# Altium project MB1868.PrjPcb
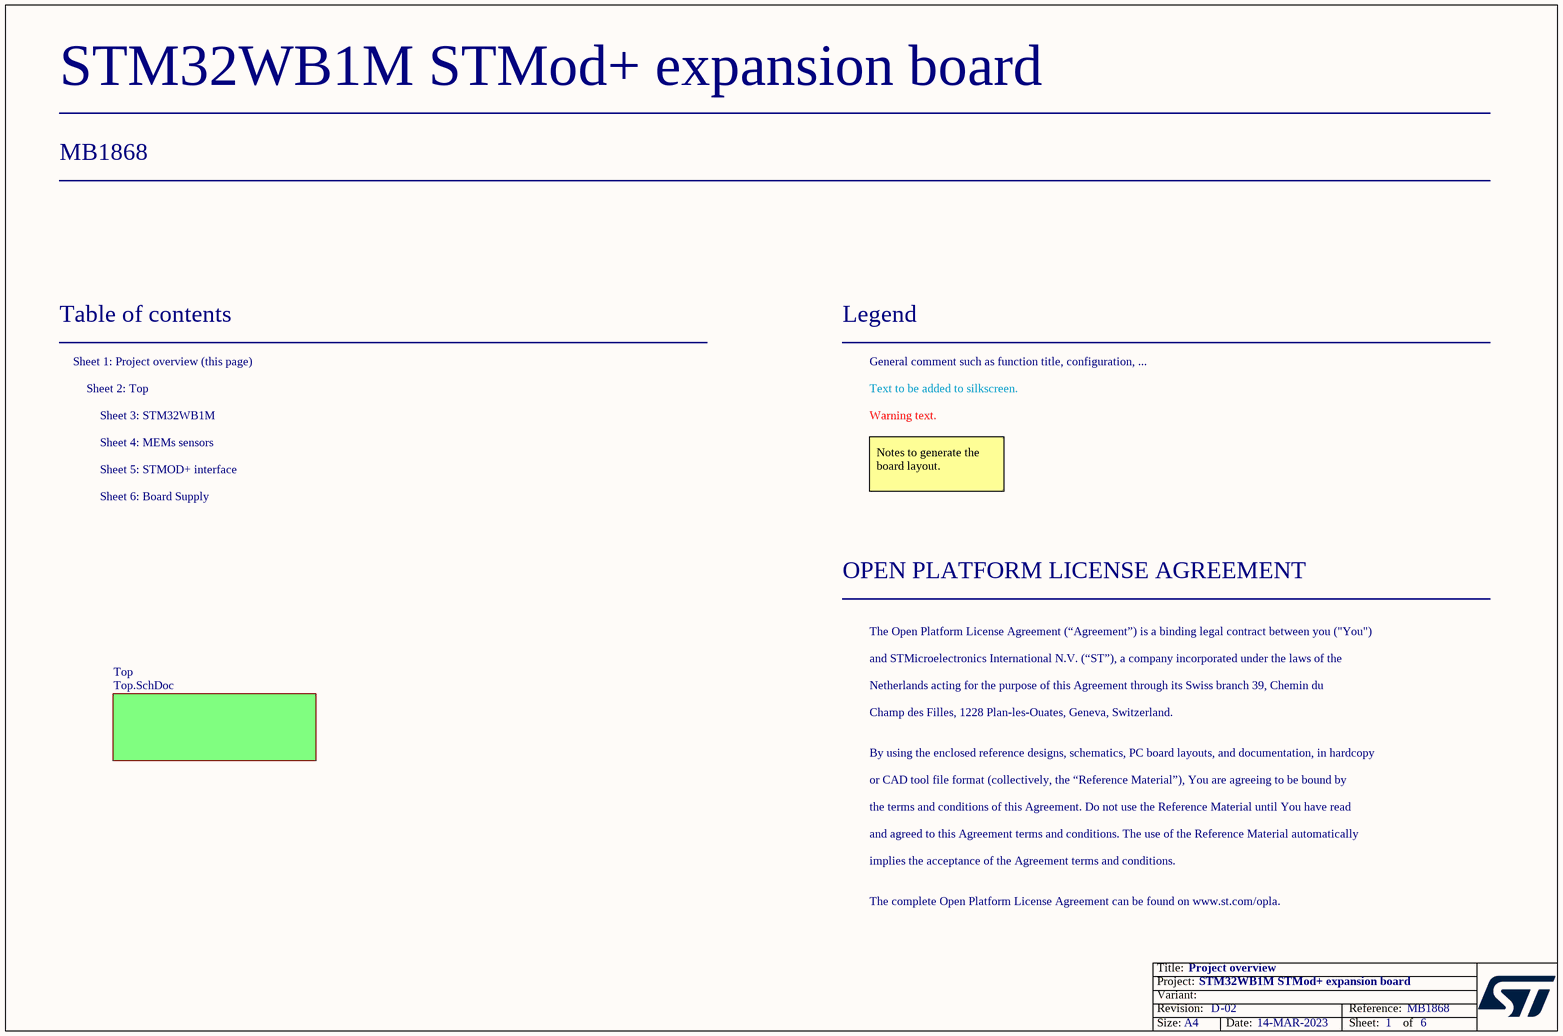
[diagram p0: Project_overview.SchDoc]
Board_Reference: MB1868; Board_PCB_Revision: D; Board_Name: STM32WB1M STMod+ expansion board; Board_Document_Date: 14-MAR-2023; Board_Assembly_Revision: 02
6 sheets, 72 parts. Net scope: flat (ports and power ports of the same name join across sheets).
Board file: MB1868.PcbDoc
Sheets:
  Project_overview.SchDoc
    Top = Top.SchDoc
      U_Mems = Mems.SchDoc
      U_STM32WB1M = STM32WB1M.SchDoc
      U_Board_supply = Board_supply.SchDoc
      U_STMOD+_interface = STMOD+_interface.SchDoc

## Sheet Project_overview.SchDoc: Project overview
size A4; Date: Not used; ApprovedBy: Not used; CheckedBy: Not used; Author: Not used; CompanyName: STMicroelectronics; DrawnBy: Not used; Engineer: Not used; Organization: Not used; Address1: Not used; Address2: Not used; Address3: Not used; Address4: Not used; DocumentNumber: Not used; Revision: Not used; SheetNumber: 1; SheetTotal: 6

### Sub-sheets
Top = Top.SchDoc: no entries

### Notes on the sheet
- Table of contents
- Sheet 1: Project overview (this page)
- Legend
- General comment such as function title, configuration, ...
- Sheet 2: Top
- Sheet 3: STM32WB1M
- Sheet 4: MEMs sensors
- Text to be added to silkscreen.
- Warning text.
- Sheet 6: Board Supply
- Sheet 5: STMOD+ interface
- Notes to generate the board layout.
- OPEN PLATFORM LICENSE AGREEMENT
- The Open Platform License Agreement (“Agreement”) is a binding legal contract between you ("You")
- and STMicroelectronics International N.V. (“ST”), a company incorporated under the laws of the
- Netherlands acting for the purpose of this Agreement through its Swiss branch 39, Chemin du
- Champ des Filles, 1228 Plan-les-Ouates, Geneva, Switzerland.
- By using the enclosed reference designs, schematics, PC board layouts, and documentation, in hardcopy
- or CAD tool file format (collectively, the “Reference Material”), You are agreeing to be bound by
- the terms and conditions of this Agreement. Do not use the Reference Material until You have read
- and agreed to this Agreement terms and conditions. The use of the Reference Material automatically
- implies the acceptance of the Agreement terms and conditions.
- The complete Open Platform License Agreement can be found on www.st.com/opla.

## Sheet Top.SchDoc: Top hierarchical view
size A4; Date: Not used; ApprovedBy: Not used; CheckedBy: Not used; Author: Not used; CompanyName: STMicroelectronics; DrawnBy: Not used; Engineer: Not used; Organization: Not used; Address1: Not used; Address2: Not used; Address3: Not used; Address4: Not used; DocumentNumber: Not used; Revision: Not used; SheetNumber: 2; SheetTotal: 6
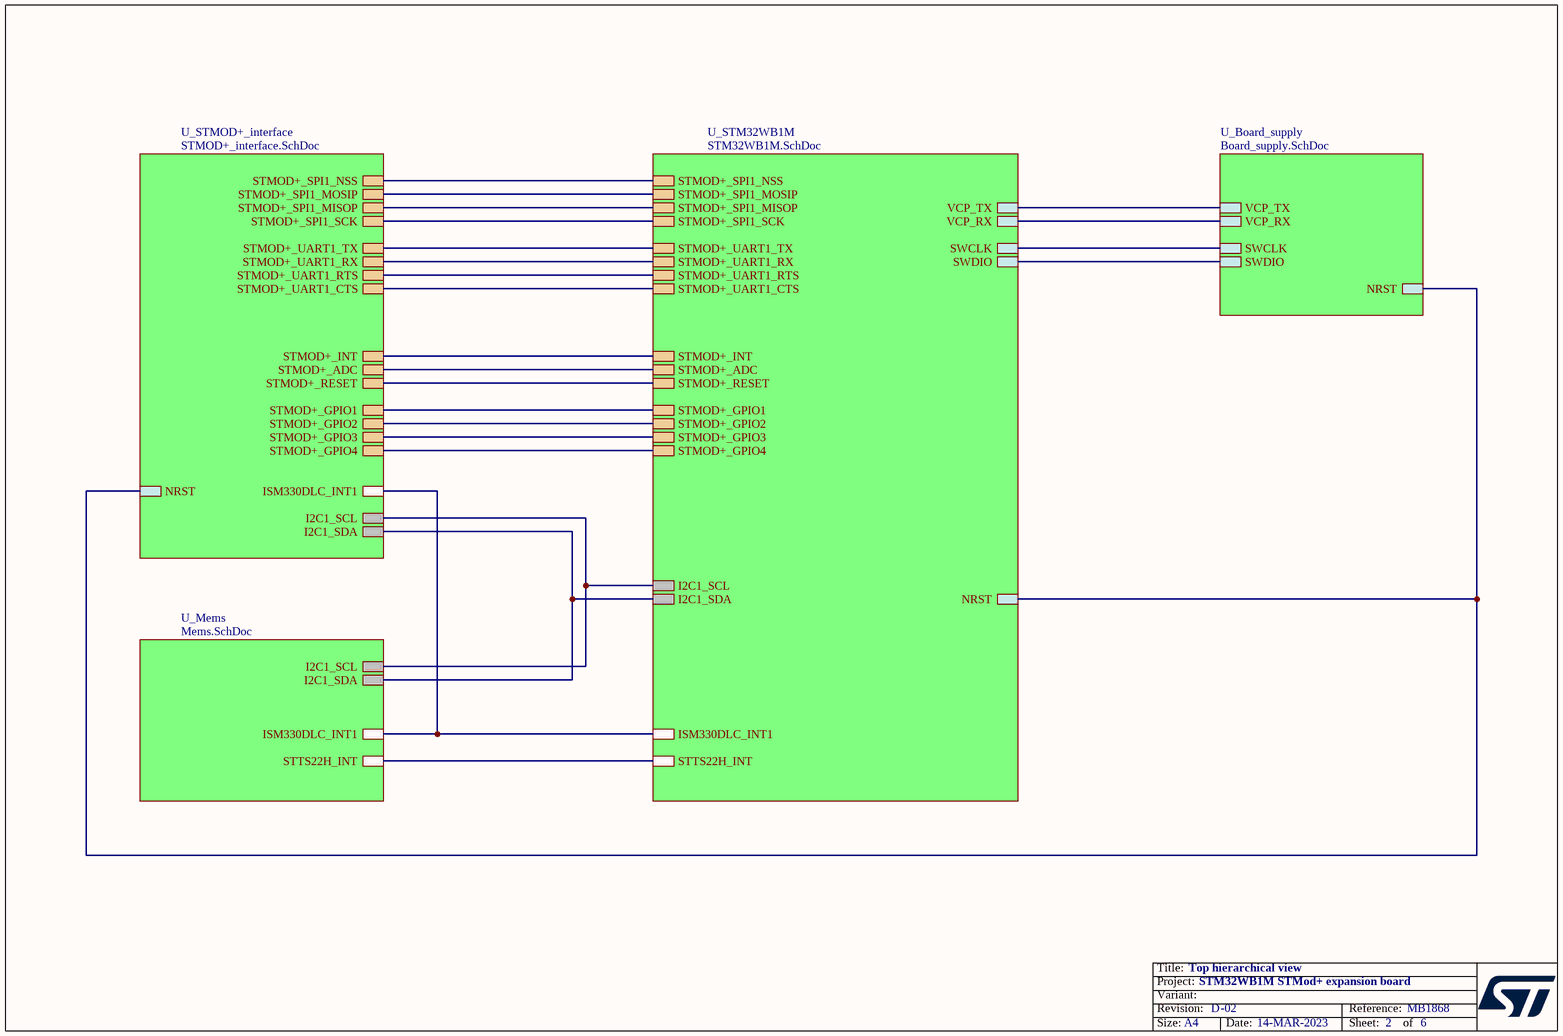
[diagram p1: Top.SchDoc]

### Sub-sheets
U_Board_supply = Board_supply.SchDoc: SWCLK, NRST, SWDIO, VCP_TX, VCP_RX
U_Mems = Mems.SchDoc: STTS22H_INT, ISM330DLC_INT1, I2C1_SCL, I2C1_SDA
U_STM32WB1M = STM32WB1M.SchDoc: VCP_TX, VCP_RX, SWCLK, SWDIO, ISM330DLC_INT1, STTS22H_INT, STMOD+_UART1_RX, STMOD+_UART1_TX, STMOD+_GPIO2, STMOD+_GPIO1, STMOD+_SPI1_SCK, STMOD+_SPI1_MOSIP, STMOD+_RESET, STMOD+_GPIO3, STMOD+_SPI1_NSS, STMOD+_UART1_RTS, STMOD+_INT, STMOD+_ADC, STMOD+_UART1_CTS, STMOD+_SPI1_MISOP, NRST, I2C1_SCL, I2C1_SDA, STMOD+_GPIO4
U_STMOD+_interface = STMOD+_interface.SchDoc: I2C1_SCL, I2C1_SDA, STMOD+_SPI1_MOSIP, STMOD+_UART1_TX, STMOD+_UART1_RX, STMOD+_SPI1_SCK, STMOD+_UART1_RTS, STMOD+_GPIO1, STMOD+_SPI1_NSS, STMOD+_INT, STMOD+_GPIO3, STMOD+_RESET, STMOD+_GPIO2, NRST, ISM330DLC_INT1, STMOD+_ADC, STMOD+_UART1_CTS, STMOD+_SPI1_MISOP, STMOD+_GPIO4

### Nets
(unnamed): sheet U_Mems/STTS22H_INT, sheet U_STM32WB1M/STTS22H_INT
(unnamed): sheet U_Mems/ISM330DLC_INT1, sheet U_STM32WB1M/ISM330DLC_INT1, sheet U_STMOD+_interface/ISM330DLC_INT1  [a separate net that carries the same name]
(unnamed): sheet U_Mems/I2C1_SCL, sheet U_STM32WB1M/I2C1_SCL, sheet U_STMOD+_interface/I2C1_SCL  [a separate net that carries the same name]
(unnamed): sheet U_Mems/I2C1_SDA, sheet U_STM32WB1M/I2C1_SDA, sheet U_STMOD+_interface/I2C1_SDA  [a separate net that carries the same name]
(unnamed): sheet U_STM32WB1M/VCP_TX, sheet U_Board_supply/VCP_TX  [a separate net that carries the same name]
(unnamed): sheet U_STM32WB1M/VCP_RX, sheet U_Board_supply/VCP_RX  [a separate net that carries the same name]
(unnamed): sheet U_STM32WB1M/SWCLK, sheet U_Board_supply/SWCLK  [a separate net that carries the same name]
(unnamed): sheet U_STM32WB1M/SWDIO, sheet U_Board_supply/SWDIO  [a separate net that carries the same name]
(unnamed): sheet U_STM32WB1M/STMOD+_UART1_RX, sheet U_STMOD+_interface/STMOD+_UART1_RX  [a separate net that carries the same name]
(unnamed): sheet U_STM32WB1M/STMOD+_UART1_TX, sheet U_STMOD+_interface/STMOD+_UART1_TX  [a separate net that carries the same name]
(unnamed): sheet U_STM32WB1M/STMOD+_GPIO2, sheet U_STMOD+_interface/STMOD+_GPIO2  [a separate net that carries the same name]
(unnamed): sheet U_STM32WB1M/STMOD+_GPIO1, sheet U_STMOD+_interface/STMOD+_GPIO1  [a separate net that carries the same name]
(unnamed): sheet U_STM32WB1M/STMOD+_SPI1_SCK, sheet U_STMOD+_interface/STMOD+_SPI1_SCK  [a separate net that carries the same name]
(unnamed): sheet U_STM32WB1M/STMOD+_SPI1_MOSIP, sheet U_STMOD+_interface/STMOD+_SPI1_MOSIP  [a separate net that carries the same name]
(unnamed): sheet U_STM32WB1M/STMOD+_RESET, sheet U_STMOD+_interface/STMOD+_RESET  [a separate net that carries the same name]
(unnamed): sheet U_STM32WB1M/STMOD+_GPIO3, sheet U_STMOD+_interface/STMOD+_GPIO3  [a separate net that carries the same name]
(unnamed): sheet U_STM32WB1M/STMOD+_SPI1_NSS, sheet U_STMOD+_interface/STMOD+_SPI1_NSS  [a separate net that carries the same name]
(unnamed): sheet U_STM32WB1M/STMOD+_UART1_RTS, sheet U_STMOD+_interface/STMOD+_UART1_RTS  [a separate net that carries the same name]
(unnamed): sheet U_STM32WB1M/STMOD+_INT, sheet U_STMOD+_interface/STMOD+_INT  [a separate net that carries the same name]
(unnamed): sheet U_STM32WB1M/STMOD+_ADC, sheet U_STMOD+_interface/STMOD+_ADC  [a separate net that carries the same name]
(unnamed): sheet U_STM32WB1M/STMOD+_UART1_CTS, sheet U_STMOD+_interface/STMOD+_UART1_CTS  [a separate net that carries the same name]
(unnamed): sheet U_STM32WB1M/STMOD+_SPI1_MISOP, sheet U_STMOD+_interface/STMOD+_SPI1_MISOP  [a separate net that carries the same name]
(unnamed): sheet U_STM32WB1M/NRST, sheet U_Board_supply/NRST, sheet U_STMOD+_interface/NRST  [a separate net that carries the same name]
(unnamed): sheet U_STM32WB1M/STMOD+_GPIO4, sheet U_STMOD+_interface/STMOD+_GPIO4  [a separate net that carries the same name]

## Sheet Mems.SchDoc: Mems Sensors
size A4; Date: Not used; ApprovedBy: Not used; CheckedBy: Not used; Author: Not used; CompanyName: STMicroelectronics; DrawnBy: Not used; Engineer: Not used; Organization: Not used; Address1: Not used; Address2: Not used; Address3: Not used; Address4: Not used; DocumentNumber: Not used; Revision: Not used; SheetNumber: 5; SheetTotal: 6
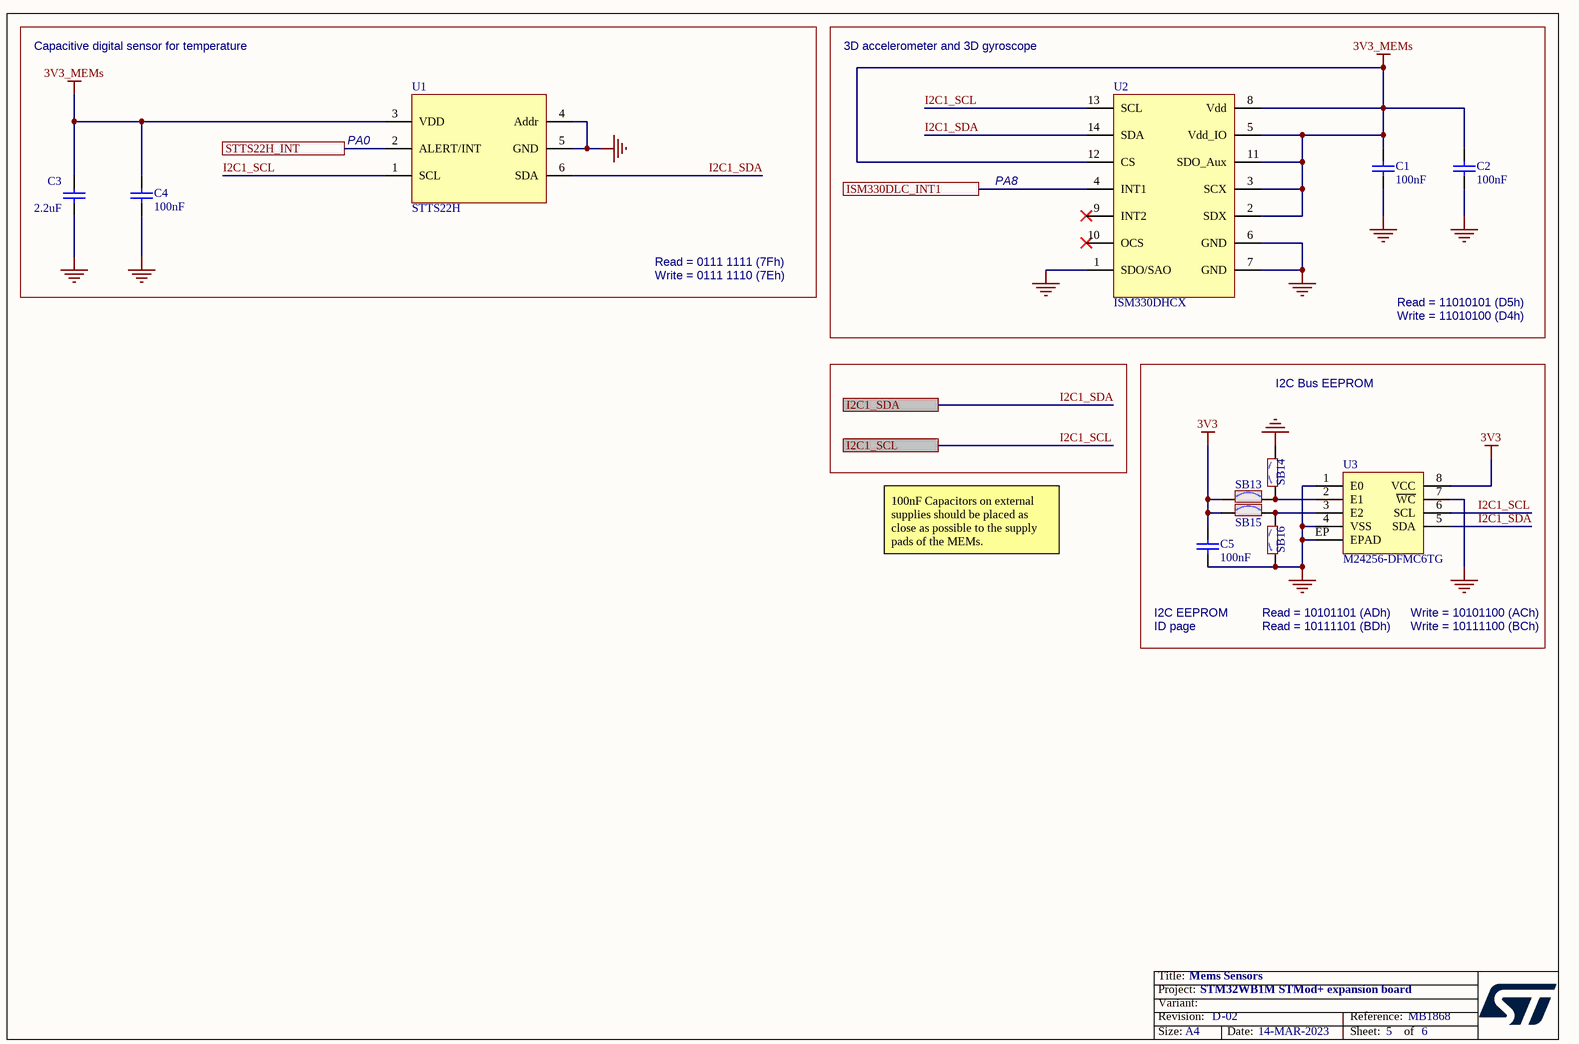
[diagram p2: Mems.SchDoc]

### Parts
C1  value 100nF  [C0402]  (hidden comment: Capacitor)
C2  value 100nF  [C0402]  (hidden comment: Capacitor)
C3  value 2.2uF  [C0402]  (hidden comment: Capacitor)
C4  value 100nF  [C0402]  (hidden comment: Capacitor)
C5  value 100nF  [C0402]  (hidden comment: Capacitor)
SB13  SB_ON  [SOLDER-BRIDGE_R0402-0R]  (value not drawn)
SB14  SB_OFF  [SOLDER-BRIDGE_R0402-0R]  (value not drawn)
SB15  SB_ON  [SOLDER-BRIDGE_R0402-0R]  (value not drawn)
SB16  SB_OFF  [SOLDER-BRIDGE_R0402-0R]  (value not drawn)
U1  STTS22H  [ICC_UDFN6-EPAD_2X2_P065]
U2  ISM330DHCX  [ICC_LGA14_3X2P5_P050]
U3  value M24256-DFMC6TG  [ICC_DFN8-EPAD_2X3_P050]  (hidden comment: M24128-DFMC6TP)

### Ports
I2C1_SCL, I2C1_SDA, ISM330DLC_INT1, STTS22H_INT

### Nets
3V3: C5.2 SB13.1 SB15.1 U3.8(VCC)
3V3_MEMs: C1.2 C2.2 C3.2 C4.2 U1.3(VDD) U2.2(SDX) U2.3(SCX) U2.5(Vdd_IO) U2.8(Vdd) U2.11(SDO_Aux) U2.12(CS)
GND: C1.1 C2.1 C3.1 C4.1 C5.1 SB14.1 SB16.2 U1.4(Addr) U1.5(GND) U2.1(SDO/SAO) U2.6(GND) U2.7(GND) U3.1(E0) U3.4(VSS) U3.7(~{WC}) U3.EP(EPAD)
I2C1_SCL: U1.1(SCL) U2.13(SCL) U3.6(SCL) ; port I2C1_SCL
I2C1_SDA: U1.6(SDA) U2.14(SDA) U3.5(SDA) ; port I2C1_SDA
PA0: U1.2(ALERT/INT) ; port STTS22H_INT
PA8: U2.4(INT1) ; port ISM330DLC_INT1
NetSB13_2: SB13.2 SB14.2 U3.2(E1)
NetSB15_2: SB15.2 SB16.1 U3.3(E2)

Not connected (* = marked no-connect by the designer): U2 9(INT2)* 10(OCS)*

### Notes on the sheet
- Capacitive digital sensor for temperature
- 3D accelerometer and 3D gyroscope
- (near U1) PA0
- PA8
- Read = 0111 1111 (7Fh)
- Write = 0111 1110 (7Eh)
- Read = 11010101 (D5h)
- Write = 11010100 (D4h)
- I2C Bus EEPROM
- 100nF Capacitors on external supplies should be placed as close as possible to the supply pads of the MEMs.
- I2C EEPROM
- ID page
- Read = 10101101 (ADh)
- Read = 10111101 (BDh)
- Write = 10101100 (ACh)
- Write = 10111100 (BCh)

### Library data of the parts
C1 C2 C4 C5 = MCD-00006: Capacitor, MLCC, 100nF, 16V, X7R, +/-10%, 0402, T=0.5mm; Part_Preference: Recommended; Manufacturer: YAGEO; Manufacturer_Part_Number: CC0402KRX7R7BB104; Partial_Alternate_Internal_Part_Number: MCD-03299; Order_Code_RS: 616-9701; Component_Country_Of_Origin: China; ShowFields: YES; ID: 2474
C3 = MCD-01823: Capacitor, MLCC, 2.2uF, 6V3, X5R,+/-10%, 0402, T=0.5mm; Manufacturer_Part_Number: GRM155R60J225KE95D; Manufacturer: MURATA; Part_Preference: Recommended; Order_Code_RS: 172-6478
SB13 SB15 = MCD-01618: Solder Bridge 0402 ON; Part_Type: Misc; Manufacturer_Part_Number: RC0402JR-070RL; Manufacturer: YAGEO; Part_Preference: Recommended; Order_Code_RS: 618-5804
SB14 SB16 = MCD-02162: Solder Bridge 0402 OFF; Part_Type: Misc; Part_Preference: Recommended; Manufacturer: YAGEO; Manufacturer_Part_Number: RC0402JR-070RL; Order_Code_RS: 618-5804
U1 = MCD-02159: temperature sensor; Part_Type: IC; Part_Preference: Recommended; Manufacturer: STMICROELECTRONICS; Manufacturer_HQ_COO: EU; Order_code_RS: 194-7646; Component_Country_Of_Origin: Thailand
U2 = MCD-02160: iNEMO inertial module: 3D accelerometer and 3D gyroscope, with digital output for industrial applications; Part_Type: IC; Part_Preference: Recommended; Manufacturer: STMICROELECTRONICS; Manufacturer_HQ_COO: EU; Order_code_RS: ISM330DHCXTR; Component_Country_Of_Origin: Malta, Philippines
U3 = MCD-01871: I2C Memory 3V3, 256Kbits, 2x3,0.55mm, UFDFPN8; Part_Type: IC; Manufacturer: STMICROELECTRONICS; BMS_Part_Number: 9175665; Part_Preference: Recommended; Manufacturer_HQ_COO: EU

## Sheet STM32WB1M.SchDoc: STM32WB1M
size A4; Date: Not used; ApprovedBy: Not used; CheckedBy: Not used; Author: Not used; CompanyName: STMicroelectronics; DrawnBy: Not used; Engineer: Not used; Organization: Not used; Address1: Not used; Address2: Not used; Address3: Not used; Address4: Not used; DocumentNumber: Not used; Revision: Not used; SheetNumber: 3; SheetTotal: 6
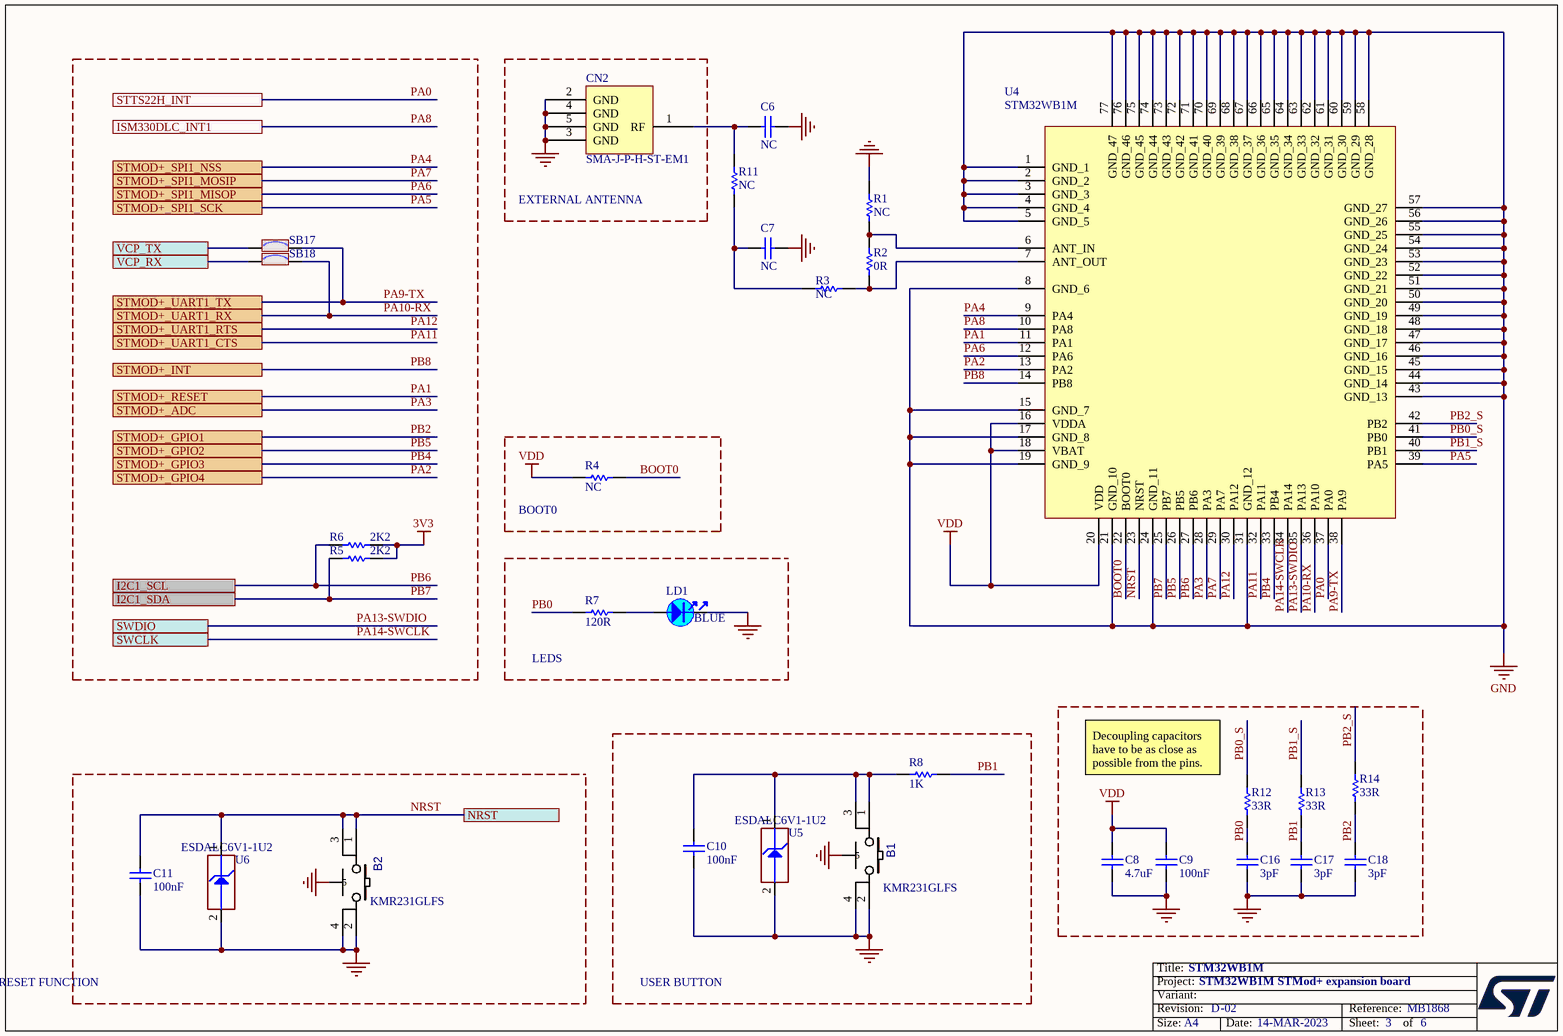
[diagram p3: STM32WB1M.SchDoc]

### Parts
B1  value KMR231GLFS  [SWI_C&K_Y78B23110FP__ITT_KMR231GLFS]
B2  value KMR231GLFS  [SWI_C&K_Y78B23110FP__ITT_KMR231GLFS]
C6  value NC  [C0402]  (hidden comment: Capacitor)
C7  value NC  [C0402]  (hidden comment: Capacitor)
C8  value 4.7uF  [C0603]
C9  value 100nF  [C0402]  (hidden comment: Capacitor)
C10  value 100nF  [C0402]  (hidden comment: Capacitor)
C11  value 100nF  [C0402]  (hidden comment: Capacitor)
C16  value 3pF  [CC0201CRNPO8BN3R0]  (hidden comment: Capacitor)
C17  value 3pF  [CC0201CRNPO8BN3R0]  (hidden comment: Capacitor)
C18  value 3pF  [CC0201CRNPO8BN3R0]  (hidden comment: Capacitor)
CN2  value SMA-J-P-H-ST-EM1  [CON_SAMTEC_SMA-J-P-X-ST-EM1]
LD1  value BLUE  [LED_0603_OSRAM_LB-Q39G-L2OO-35-1_BLUE_1A2K_H0P4]
R1  value NC  [R0201_H0P23]  (hidden comment: Resistor)
R2  value 0R  [R0201_H0P23]  (hidden comment: Resistor)
R3  value NC  [R0201_H0P23]  (hidden comment: Resistor)
R4  value NC  [R0402]
R5  value 2K2  [R0402]  (hidden comment: Resistor)
R6  value 2K2  [R0402]  (hidden comment: Resistor)
R7  value 120R  [R0402]
R8  value 1K  [R0402]
R11  value NC  [R0402]  (hidden comment: Resistor)
R12  value 33R  [R0201_H0P23]  (hidden comment: Resistor)
R13  value 33R  [R0201_H0P23]  (hidden comment: Resistor)
R14  value 33R  [R0201_H0P23]  (hidden comment: Resistor)
SB17  SB_ON  [SOLDER-BRIDGE_R0402-0R]  (value not drawn)
SB18  SB_ON  [SOLDER-BRIDGE_R0402-0R]  (value not drawn)
U4  STM32WB1M  [ICC_LBA77_6P5X10_P0P45]
U5  value ESDALC6V1-1U2  [ESD_ST0201]
U6  value ESDALC6V1-1U2  [ESD_ST0201]

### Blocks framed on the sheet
EXTERNAL ANTENNA: CN2
BOOT0: R4
LEDS: LD1 R7
USER BUTTON: B1 C10 R8 U5
RESET FUNCTION: B2 C11 U6

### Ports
I2C1_SCL, I2C1_SDA, ISM330DLC_INT1, NRST, STMOD+_ADC, STMOD+_GPIO1, STMOD+_GPIO2, STMOD+_GPIO3, STMOD+_GPIO4, STMOD+_INT, STMOD+_RESET, STMOD+_SPI1_MISOP, STMOD+_SPI1_MOSIP, STMOD+_SPI1_NSS, STMOD+_SPI1_SCK, STMOD+_UART1_CTS, STMOD+_UART1_RTS, STMOD+_UART1_RX, STMOD+_UART1_TX, STTS22H_INT, SWCLK, SWDIO, VCP_RX, VCP_TX

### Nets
3V3: R5.2 R6.2
GND: B1.2 B1.4 B1.5 B2.2 B2.4 B2.5 C6.2 C7.2 C8.1 C9.1 C10.1 C11.1 C16.1 C17.1 C18.1 CN2.2(GND) CN2.3(GND) CN2.4(GND) CN2.5(GND) LD1.2 R1.2 U4.1(GND_1) U4.2(GND_2) U4.3(GND_3) U4.4(GND_4) U4.5(GND_5) U4.8(GND_6) U4.15(GND_7) U4.17(GND_8) U4.19(GND_9) U4.21(GND_10) U4.24(GND_11) U4.31(GND_12) U4.43(GND_13) U4.44(GND_14) U4.45(GND_15) U4.46(GND_16) U4.47(GND_17) U4.48(GND_18) U4.49(GND_19) U4.50(GND_20) U4.51(GND_21) U4.52(GND_22) U4.53(GND_23) U4.54(GND_24) U4.55(GND_25) U4.56(GND_26) U4.57(GND_27) U4.58(GND_28) U4.59(GND_29) U4.60(GND_30) U4.61(GND_31) U4.62(GND_32) U4.63(GND_33) U4.64(GND_34) U4.65(GND_35) U4.66(GND_36) U4.67(GND_37) U4.68(GND_38) U4.69(GND_39) U4.70(GND_40) U4.71(GND_41) U4.72(GND_42) U4.73(GND_43) U4.74(GND_44) U4.75(GND_45) U4.76(GND_46) U4.77(GND_47) U5.2(GND) U6.2(GND)
VDD: C8.2 C9.2 R4.1 U4.16(VDDA) U4.18(VBAT) U4.20(VDD)
BOOT0: R4.2 U4.22(BOOT0)
NRST: B2.1 B2.3 C11.2 U4.23(NRST) U6.1(IO1) ; port NRST
PA0: U4.37(PA0) ; port STTS22H_INT
PA1: U4.11(PA1) ; port STMOD+_RESET
PA2: U4.13(PA2) ; port STMOD+_GPIO4
PA3: U4.28(PA3) ; port STMOD+_ADC
PA4: U4.9(PA4) ; port STMOD+_SPI1_NSS
PA5: U4.39(PA5) ; port STMOD+_SPI1_SCK
PA6: U4.12(PA6) ; port STMOD+_SPI1_MISOP
PA7: U4.29(PA7) ; port STMOD+_SPI1_MOSIP
PA8: U4.10(PA8) ; port ISM330DLC_INT1
PA9-TX: SB17.2 U4.38(PA9) ; port STMOD+_UART1_TX
PA10-RX: SB18.2 U4.36(PA10) ; port STMOD+_UART1_RX
PA11: U4.32(PA11) ; port STMOD+_UART1_CTS
PA12: U4.30(PA12) ; port STMOD+_UART1_RTS
PA13-SWDIO: U4.35(PA13) ; port SWDIO
PA14-SWCLK: U4.34(PA14) ; port SWCLK
PB0: C16.2 R7.1 R12.1
PB0_S: R12.2 U4.41(PB0)
PB1: C17.2 R8.2 R13.1
PB1_S: R13.2 U4.40(PB1)
PB2: C18.2 R14.1 ; port STMOD+_GPIO1
PB2_S: R14.2 U4.42(PB2)
PB4: U4.33(PB4) ; port STMOD+_GPIO3
PB5: U4.26(PB5) ; port STMOD+_GPIO2
PB6: R6.1 U4.27(PB6) ; port I2C1_SCL  [project net I2C1_SCL]
PB7: R5.1 U4.25(PB7) ; port I2C1_SDA  [project net I2C1_SDA]
PB8: U4.14(PB8) ; port STMOD+_INT
VCP_RX: SB18.1 ; port VCP_RX
VCP_TX: SB17.1 ; port VCP_TX
NetB1_1: B1.1 B1.3 C10.2 R8.1 U5.1(IO1)
NetC6_1: C6.1 CN2.1(RF) R11.2
NetC7_1: C7.1 R3.1 R11.1
NetLD1_1: LD1.1 R7.2
NetR1_1: R1.1 R2.2 U4.6(ANT_IN)
NetR2_1: R2.1 R3.2 U4.7(ANT_OUT)

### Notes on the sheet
- (near R12) Decoupling capacitors have to be as close as possible from the pins.

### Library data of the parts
B1 B2 = MCD-01485: Microminiature Tact Switch for SMT - KMR 2 Series - 1.9 mm height; Part_Type: Misc; Manufacturer: C&K; Provided_By: SUBCO
C6 C7 = MCD-01995: Capacitor, MLCC, 22pF, 50V, C0G, +/-5%, 0402, T=0.5mm; Part_Preference: Recommended; Manufacturer: TDK; Manufacturer_Part_Number: C1005NP01H220J050BA
C8 = MCD-00009: Capacitor, MLCC, 4.7uF, 16V, X5R, 10%, 0603, T=0.8mm; Manufacturer_Part_Number: CC0603KRX5R7BB475; Manufacturer: YAGEO; Provided_By: SUBCO
C9-C11 = MCD-00006: as C1 on sheet Mems
C16-C18 = MCD-03692: Capacitor, MLCC, 3pF, 25V, NPO, +/-0.25pF, 0201, T=0.3mm; Part_Preference: Recommended; Manufacturer: YAGEO; ShowFields: YES; ID: 5808
CN2 = MCD-00279: RF SMA connector PCB edge; Manufacturer: SAMTEC; Provided_By: SUBCO
LD1 = MCD-00585: LED Blue, 0603 SMD, Forward Voltage Min=2,8V, Max=3,8V; Part_Type: Display; Manufacturer_Part_Number: LB Q39G-L2OO-35-1; Manufacturer: OSRAM OPTO SEMICONDUCTORS; Order_Code_RS: 9148643; Provided_By: SUBCO
R1 R3 = MCD-02253: Resistor, 0R, 0201, +/-1%, 1/20W; Part_Preference: Recommended; Manufacturer: YAGEO; Manufacturer_Part_Number: RC0201FR-070RL
R2 = MCD-02450: Resistor, 0R, 0201, 1/20W; Part_Preference: Recommended; Manufacturer: YAGEO; Manufacturer_Part_Number: RC0201JR-070RP; Component_Country_Of_Origin: China; ShowFields: YES; ID: 4556
R4 R7 = MCD-00194: Resistor,120R,0402,1%,1/16W; Manufacturer_Part_Number: RC0402FR-07120RL; Manufacturer: YAGEO; Provided_By: SUBCO
R5 R6 = MCD-00057: Resistor, 2K2, 0402, +/-1%, 1/16W; Part_Preference: Recommended; Manufacturer: YAGEO; Manufacturer_Part_Number: RC0402FR-072K2L; Component_Country_Of_Origin: China; ShowFields: YES; ID: 2534
R8 = MCD-00061: Resistor,1K,0402,1%,1/16W; Manufacturer_Part_Number: RC0402FR-071KL; Manufacturer: YAGEO; Provided_By: SUBCO
R11 = MCD-02253: Resistor, 0R, 0402, +/-1%, 1/16W; Part_Preference: Recommended; Manufacturer: YAGEO; Manufacturer_Part_Number: RC0402JR-070RL
R12-R14 = MCD-03049: Resistor, 33R, 0201, +/-1%, 1/20W; Part_Preference: Recommended; Manufacturer: YAGEO; Manufacturer_Part_Number: RC0201FR-0733RL; Order_Code_RS: 198-7603; ShowFields: YES; ID: 5165
SB17 SB18 = MCD-01618: Solder Bridge 0402 ON; Part_Type: Misc; Part_Preference: Recommended; Manufacturer: YAGEO; Manufacturer_Part_Number: RC0402JR-070RL; Order_Code_RS: 618-5804
U4 = MCD-02528: STM32 BLE module based on STM32WB15; Part_Type: Misc; Part_Preference: Recommended; Manufacturer: STMICROELECTRONICS
U5 U6 = MCD-00170: ESD protection 6V1; Part_Type: Diode; Manufacturer: STMICROELECTRONICS; BMS_Part_Number: 9151132; Provided_By: SUBCO with ST control

## Sheet Board_supply.SchDoc: Board Supply
size A4; Date: Not used; ApprovedBy: Not used; CheckedBy: Not used; CompanyName: STMicroelectronics; DrawnBy: Not used; Engineer: Not used; Organization: Not used; Address1: Not used; Address2: Not used; Address3: Not used; Address4: Not used; DocumentNumber: Not used; Revision: Not used; SheetNumber: 6; SheetTotal: 6
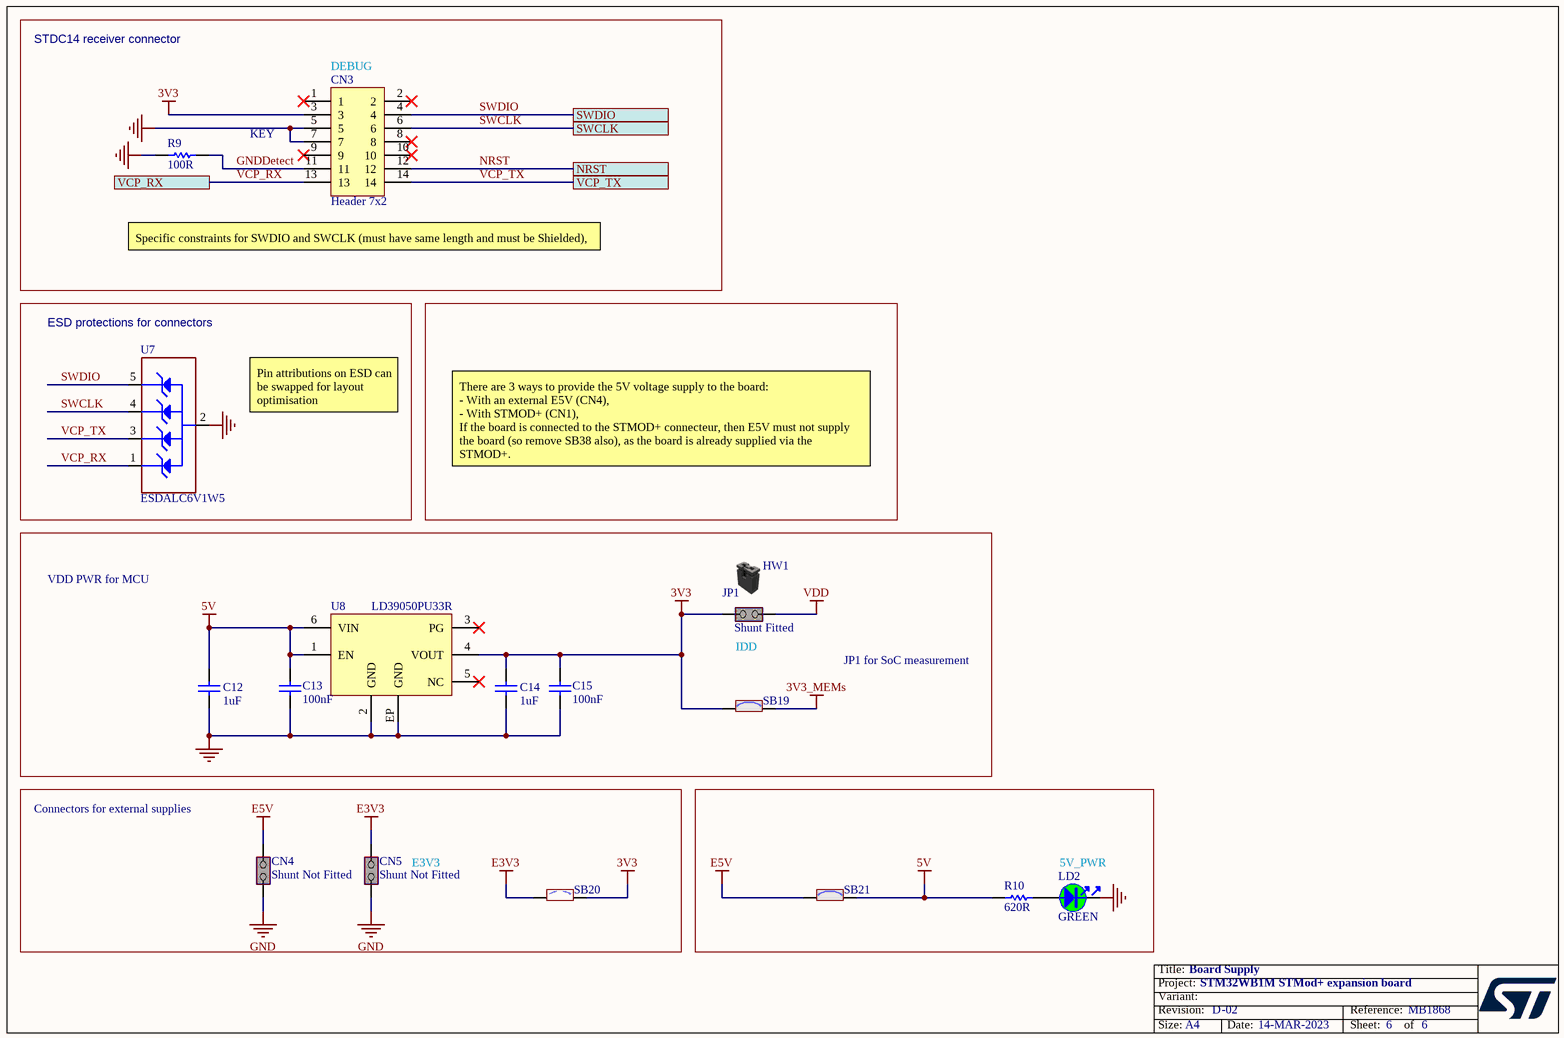
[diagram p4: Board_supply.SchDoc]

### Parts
C12  value 1uF  [C0603]
C13  value 100nF  [C0402]  (hidden comment: Capacitor)
C14  value 1uF  [C0603]
C15  value 100nF  [C0402]  (hidden comment: Capacitor)
CN3  Header 7x2  [CON_STDC14_Receiver_SMALL]
CN4  value Shunt Not Fitted  [CON_SAMTEC_TSW-102-07-G-S]
CN5  value Shunt Not Fitted  [CON_SAMTEC_TSW-102-07-G-S]
HW1  (no value)  (mechanical)
JP1  value Shunt Fitted  [CON_SAMTEC_TSW-102-07-G-S]
LD2  value GREEN  [LED_0603_OSRAM_LG-Q396-PS-35_GREEN_1A2K_H0P4]
R9  value 100R  [R0402]  (hidden comment: Resistor)
R10  value 620R  [R0402]
SB19  SB_ON  [SOLDER-BRIDGE_R0402-0R]  (value not drawn)
SB20  SB_OFF  [SOLDER-BRIDGE_R0402-0R]  (value not drawn)
SB21  SB_ON  [SOLDER-BRIDGE_R0402-0R]  (value not drawn)
U7  value ESDALC6V1W5  [ESD_SOT323-5L]
U8  value LD39050PU33R  [ICC_DFN6-EPAD_3X3_P095]

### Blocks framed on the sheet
ESD protections for connectors: U7
5V_PWR: LD2 R10 SB21

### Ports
NRST, SWCLK, SWDIO, VCP_RX, VCP_TX

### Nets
3V3: C14.2 C15.2 CN3.3 JP1.1(COMMON) SB19.1 SB20.2 U8.4(VOUT)
3V3_MEMs: SB19.2
5V: C12.2 C13.2 R10.1 SB21.2 U8.1(EN) U8.6(VIN)
E3V3: CN5.2(NO) SB20.1
E5V: CN4.2(NO) SB21.1
GND: C12.1 C13.1 C14.1 C15.1 CN3.5 CN3.7 CN4.1(COMMON) CN5.1(COMMON) LD2.2 R9.1 U7.2(GND) U8.2(GND) U8.EP(GND)
VDD: JP1.2(NO)
GNDDetect: CN3.11 R9.2
NRST: CN3.12 ; port NRST
SWCLK: CN3.6 U7.4(IO3) ; port SWCLK  [project net PA14-SWCLK]
SWDIO: CN3.4 U7.5(IO4) ; port SWDIO  [project net PA13-SWDIO]
VCP_RX: CN3.13 U7.1(IO1) ; port VCP_RX
VCP_TX: CN3.14 U7.3(IO2) ; port VCP_TX
NetLD2_1: LD2.1 R10.2

Not connected (* = marked no-connect by the designer): CN3 1* 2* 8* 9* 10*; U8 3(PG)* 5(NC)*

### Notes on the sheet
- STDC14 receiver connector
- (near CN3) DEBUG
- KEY
- (near CN3) Specific constraints for SWDIO and SWCLK (must have same length and must be Shielded),
- Pin attributions on ESD can be swapped for layout optimisation
- There are 3 ways to provide the 5V voltage supply to the board:
  - With an external E5V (CN4),
  - With STMOD+ (CN1),
  If the board is connected to the STMOD+ connecteur, then E5V must not supply the board (so remove SB38 also), as the board is already supplied via the STMOD+.
- VDD PWR for MCU
- (near JP1) IDD
- JP1 for SoC measurement
- Connectors for external supplies
- (near CN5) E3V3

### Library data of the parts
C12 C14 = MCD-00010: Capacitor, MLCC, 1uF, 16V, X5R, 10%, 0603, T=0,8mm; Manufacturer_Part_Number: CC0603KRX5R7BB105; Manufacturer: YAGEO; Provided_By: SUBCO
C13 C15 = MCD-00006: as C1 on sheet Mems
CN3 = MCD-00639: Header, 7x2, 1.27mm, VR, SMD, T=5.97mm; Part_Type: Connector; Part_Preference: Recommended; Manufacturer: SAMTEC; Manufacturer_Part_Number: FTSH-107-01-L-DV-K; Order_Code_RS: 179-8765
CN4 CN5 JP1 = MCD-00683: Header, 2x1, 2,54mm, VR, TH, Height 5.84mm/2.54mm - Shunt Fitted by default; Part_Type: Connector; Manufacturer_Part_Number: TSW-102-07-x-S; Manufacturer: SAMTEC; Provided_By: SUBCO
HW1 = MCD-00043: SHUNT 2.54mm BLACK; Manufacturer_Part_Number: SNT-100-BK-G; Manufacturer: SAMTEC; Part_Type: Mechanical; Provided_By: SUBCO; Value: SNT-100-BK-G
LD2 = MCD-00588: LED Green, 0603 SMD, Forward Voltage Typ=2V, Max=2.5V; Part_Type: Display; Manufacturer_Part_Number: LG Q396-PS-35; Manufacturer: OSRAM OPTO SEMICONDUCTORS; Alternate_Manufacturer_Part_Number: VLMTG1300-GS08; Alternate_Manufacturer: VISHAY SEMICONDUCTOR OPTO DIVISION; Provided_By: SUBCO
R9 = MCD-00067: Resistor, 100R, 0402, +/- 1%, 1/16W; Part_Preference: Recommended; Manufacturer: YAGEO; Manufacturer_Part_Number: RC0402FR-07100RL; Component_Country_Of_Origin: China; ShowFields: YES; ID: 2527
R10 = MCD-00499: Resistor,620R,0402,1%,1/16W; Manufacturer_Part_Number: RC0402FR-07620RL; Manufacturer: YAGEO; Provided_By: SUBCO
SB19 SB21 = MCD-01618: as SB17 on sheet STM32WB1M
SB20 = MCD-02162: as SB14 on sheet Mems
U7 = MCD-00136: Dual Transil array for ESD protection; Part_Type: Diode; Manufacturer: STMICROELECTRONICS; BMS_Part_Number: 9151112; Provided_By: SUBCO with ST control
U8 = MCD-00215: Low quiescent current and low noise voltage regulators; Manufacturer: STMICROELECTRONICS; Part_Type: IC; BMS_Part_Number: 9176126; Provided_By: SUBCO with ST control

## Sheet STMOD+_interface.SchDoc: STMOD+ interface
size A4; Date: Not used; ApprovedBy: Not used; CheckedBy: Not used; Author: Not used; CompanyName: STMicroelectronics; DrawnBy: Not used; Engineer: Not used; Organization: Not used; Address1: Not used; Address2: Not used; Address3: Not used; Address4: Not used; DocumentNumber: Not used; Revision: Not used; SheetNumber: 4; SheetTotal: 6
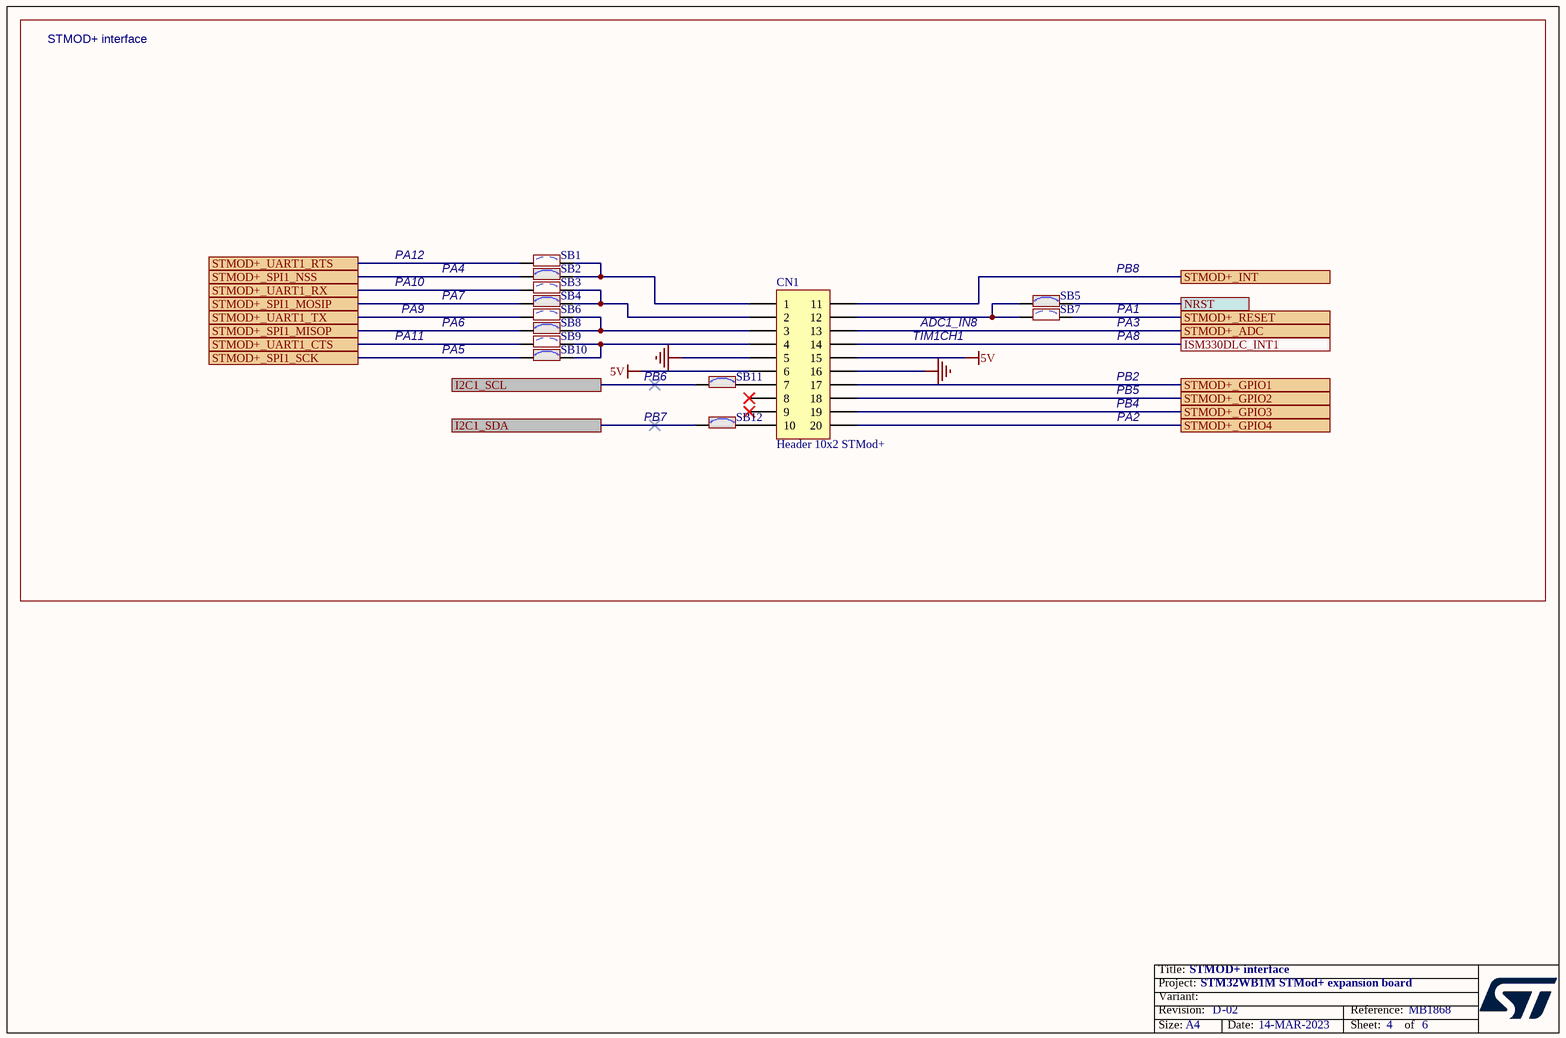
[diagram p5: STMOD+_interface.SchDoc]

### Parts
CN1  Header 10x2 STMod+  [CON_SAMTEC_TMM-110-01-L-D-RA__STMOD+]
SB1  SB_OFF  [SOLDER-BRIDGE_R0402-0R]  (value not drawn)
SB2  SB_ON  [SOLDER-BRIDGE_R0402-0R]  (value not drawn)
SB3  SB_OFF  [SOLDER-BRIDGE_R0402-0R]  (value not drawn)
SB4  SB_ON  [SOLDER-BRIDGE_R0402-0R]  (value not drawn)
SB5  SB_ON  [SOLDER-BRIDGE_R0402-0R]  (value not drawn)
SB6  SB_OFF  [SOLDER-BRIDGE_R0402-0R]  (value not drawn)
SB7  SB_OFF  [SOLDER-BRIDGE_R0402-0R]  (value not drawn)
SB8  SB_ON  [SOLDER-BRIDGE_R0402-0R]  (value not drawn)
SB9  SB_OFF  [SOLDER-BRIDGE_R0402-0R]  (value not drawn)
SB10  SB_ON  [SOLDER-BRIDGE_R0402-0R]  (value not drawn)
SB11  SB_ON  [SOLDER-BRIDGE_R0402-0R]  (value not drawn)
SB12  SB_ON  [SOLDER-BRIDGE_R0402-0R]  (value not drawn)

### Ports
I2C1_SCL, I2C1_SDA, ISM330DLC_INT1, NRST, STMOD+_ADC, STMOD+_GPIO1, STMOD+_GPIO2, STMOD+_GPIO3, STMOD+_GPIO4, STMOD+_INT, STMOD+_RESET, STMOD+_SPI1_MISOP, STMOD+_SPI1_MOSIP, STMOD+_SPI1_NSS, STMOD+_SPI1_SCK, STMOD+_UART1_CTS, STMOD+_UART1_RTS, STMOD+_UART1_RX, STMOD+_UART1_TX

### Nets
5V: CN1.6 CN1.15
GND: CN1.5 CN1.16
I2C1_SCL: SB11.1 ; port I2C1_SCL
I2C1_SDA: SB12.1 ; port I2C1_SDA
NRST: SB5.2 ; port NRST
PA1: SB7.2 ; port STMOD+_RESET
PA2: CN1.20 ; port STMOD+_GPIO4
PA3: CN1.13 ; port STMOD+_ADC
PA4: SB2.1 ; port STMOD+_SPI1_NSS
PA5: SB10.1 ; port STMOD+_SPI1_SCK
PA6: SB8.1 ; port STMOD+_SPI1_MISOP
PA7: SB4.1 ; port STMOD+_SPI1_MOSIP
PA8: CN1.14 ; port ISM330DLC_INT1
PA9-TX: SB6.1 ; port STMOD+_UART1_TX
PA10-RX: SB3.1 ; port STMOD+_UART1_RX
PA11: SB9.1 ; port STMOD+_UART1_CTS
PA12: SB1.1 ; port STMOD+_UART1_RTS
PB2: CN1.17 ; port STMOD+_GPIO1
PB4: CN1.19 ; port STMOD+_GPIO3
PB5: CN1.18 ; port STMOD+_GPIO2
PB8: CN1.11 ; port STMOD+_INT
NetCN1_1: CN1.1 SB1.2 SB2.2
NetCN1_2: CN1.2 SB3.2 SB4.2
NetCN1_3: CN1.3 SB6.2 SB8.2
NetCN1_4: CN1.4 SB9.2 SB10.2
NetCN1_7: CN1.7 SB11.2
NetCN1_10: CN1.10 SB12.2
NetCN1_12: CN1.12 SB5.1 SB7.1

Not connected (* = marked no-connect by the designer): CN1 8* 9*

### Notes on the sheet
- STMOD+ interface
- PA9
- PA12
- PA10
- PA7
- PA4
- PA1
- PB8
- PA11
- PA6
- PA5
- PB6
- TIM1CH1
- ADC1_IN8
- PA8
- PA3
- PB2
- PB7
- PB4
- PB5
- PA2

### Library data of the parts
CN1 = MCD-00288: Header 10x2, 2mm, RA, TH, Height 3.20mm/3.50mm; Part_Type: Connector; Manufacturer_Part_Number: TMM-110-01-L-D-RA; Manufacturer: SAMTEC; Provided_By: SUBCO
SB1 SB3 SB6 SB7 SB9 = MCD-02162: as SB14 on sheet Mems
SB2 SB4 SB5 SB8 SB10-SB12 = MCD-01618: as SB17 on sheet STM32WB1M

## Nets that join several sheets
3V3: Mems (C5.2 SB13.1 SB15.1 U3.8), STM32WB1M (R5.2 R6.2), Board_supply (7 pins)
3V3_MEMs: Mems (11 pins), Board_supply (SB19.2)
5V: Board_supply (6 pins), STMOD+_interface (CN1.6 CN1.15)
GND: Mems (16 pins), STM32WB1M (70 pins), Board_supply (13 pins), STMOD+_interface (CN1.5 CN1.16)
VDD: STM32WB1M (6 pins), Board_supply (JP1.2)
I2C1_SCL: Mems (U1.1 U2.13 U3.6), STM32WB1M (R6.1 U4.27), STMOD+_interface (SB11.1)
I2C1_SDA: Mems (U1.6 U2.14 U3.5), STM32WB1M (R5.1 U4.25), STMOD+_interface (SB12.1)
NRST: STM32WB1M (5 pins), Board_supply (CN3.12), STMOD+_interface (SB5.2)
PA0: Mems (U1.2), STM32WB1M (U4.37)
PA1: STM32WB1M (U4.11), STMOD+_interface (SB7.2)
PA2: STM32WB1M (U4.13), STMOD+_interface (CN1.20)
PA3: STM32WB1M (U4.28), STMOD+_interface (CN1.13)
PA4: STM32WB1M (U4.9), STMOD+_interface (SB2.1)
PA5: STM32WB1M (U4.39), STMOD+_interface (SB10.1)
PA6: STM32WB1M (U4.12), STMOD+_interface (SB8.1)
PA7: STM32WB1M (U4.29), STMOD+_interface (SB4.1)
PA8: Mems (U2.4), STM32WB1M (U4.10), STMOD+_interface (CN1.14)
PA9-TX: STM32WB1M (SB17.2 U4.38), STMOD+_interface (SB6.1)
PA10-RX: STM32WB1M (SB18.2 U4.36), STMOD+_interface (SB3.1)
PA11: STM32WB1M (U4.32), STMOD+_interface (SB9.1)
PA12: STM32WB1M (U4.30), STMOD+_interface (SB1.1)
PA13-SWDIO: STM32WB1M (U4.35), Board_supply (CN3.4 U7.5)
PA14-SWCLK: STM32WB1M (U4.34), Board_supply (CN3.6 U7.4)
PB2: STM32WB1M (C18.2 R14.1), STMOD+_interface (CN1.17)
PB4: STM32WB1M (U4.33), STMOD+_interface (CN1.19)
PB5: STM32WB1M (U4.26), STMOD+_interface (CN1.18)
PB8: STM32WB1M (U4.14), STMOD+_interface (CN1.11)
VCP_RX: STM32WB1M (SB18.1), Board_supply (CN3.13 U7.1)
VCP_TX: STM32WB1M (SB17.1), Board_supply (CN3.14 U7.3)

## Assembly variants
WB1M: not fitted C6 C7 CN2 R1 R3 R4 R11 SB1 SB3 SB6 SB7 SB9 SB14 SB16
